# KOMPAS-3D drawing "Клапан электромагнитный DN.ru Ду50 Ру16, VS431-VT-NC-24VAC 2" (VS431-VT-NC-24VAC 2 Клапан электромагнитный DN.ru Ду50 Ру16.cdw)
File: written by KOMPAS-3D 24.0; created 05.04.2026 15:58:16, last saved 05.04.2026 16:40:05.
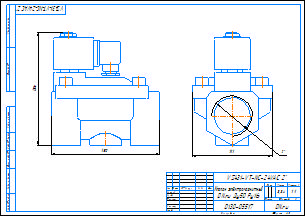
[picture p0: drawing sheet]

Document properties: c3d_UniqueCompID: ef56311e-7521-43dc-8291-0e6108b3d81d; Автор: artio; Класс точности: c; Знак неуказанной шероховатости: Шероховатость не задана; Рассекать на разрезах: Да; c3d_UniqueCompID: ef56311e-7521-43dc-8291-0e6108b3d81d; Автор: artio; Класс точности: c; Знак неуказанной шероховатости: Шероховатость не задана; Рассекать на разрезах: Да; c3d_UniqueCompID: ef56311e-7521-43dc-8291-0e6108b3d81d; Автор: artio; Класс точности: c; Знак неуказанной шероховатости: Шероховатость не задана; Рассекать на разрезах: Да; c3d_UniqueCompID: ef56311e-7521-43dc-8291-0e6108b3d81d; Автор: artio; Класс точности: c; Знак неуказанной шероховатости: Шероховатость не задана; Рассекать на разрезах: Да; c3d_UniqueCompID: ef56311e-7521-43dc-8291-0e6108b3d81d; Автор: artio; Класс точности: c; Знак неуказанной шероховатости: Шероховатость не задана; Рассекать на разрезах: Да; Автор: artio; Форматы листов документа: A3; Полное имя файла: VS431-VT-NC-24VAC 2 Клапан электромагнитный DN.ru Ду50 Ру16.m3d; Масса: 3.341; Наименование: Клапан электромагнитный DN.ru Ду50 Ру16; Количество листов документа: 1; Примечание: D130-05517

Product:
- Body: Тело 1  | qty 1
    Масса: 6.703651
- Part/product: Клапан электромагнитный DN.ru Ду50 Ру16  | designation VS431-VT-NC-24VAC 2
    Масса: 3.341
    Раздел спецификации: Прочие изделия
    Примечание: D130-05517
    additional columns: ef56311e-7521-43dc-8291-0e6108b3d81d; artio; c; Шероховатость не задана; Да

Views: Вид 1, Спереди
Referenced files in C:\Users\artio\OneDrive\Рабочий стол\Клапан электромагнитный DN.ru\VS431\VS431-ET-NC\: VS431-ET-NC-24VAC 3-4 Клапан электромагнитный DN.ru Ду20 Ру16.m3d, VS431-ET-NC-24VAC 3-4 Клапан электромагнитный DN.ru Ду20 Ру16.cdw
Referenced files in C:\Users\artio\OneDrive\Рабочий стол\Клапан электромагнитный DN.ru\VS431\VS431-VT-NC\: VS431-VT-NC-24VAC 2 Клапан электромагнитный DN.ru Ду50 Ру16.m3d
Referenced files in C:\Users\artio\OneDrive\Рабочий стол\Клапан электромагнитный DN.ru\VS431\VS431-VT-NC\VS431-VT-NC-24VAC\Ду50\: VS431-VT-NC-24VAC 2 Клапан электромагнитный DN.ru Ду50 Ру16.m3d
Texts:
  VS431-VT-NC-24VAC 2
  Клапан электромагнитный
  DN.ru Ду50 Ру16
  VS431-VT-NC-24VAC 2"
  VS431-VT-NC-24VAC 2"-
  Клапан электромагнитный DN.ru Ду50 Ру16
  VS431-VT-NC-24VAC 2 Клапан электромагнитный DN.ru Ду50 Ру16
Dimensions and other numbers on the sheet: 0; 3; 2; 4; 111; 1:1; 1; 3,34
